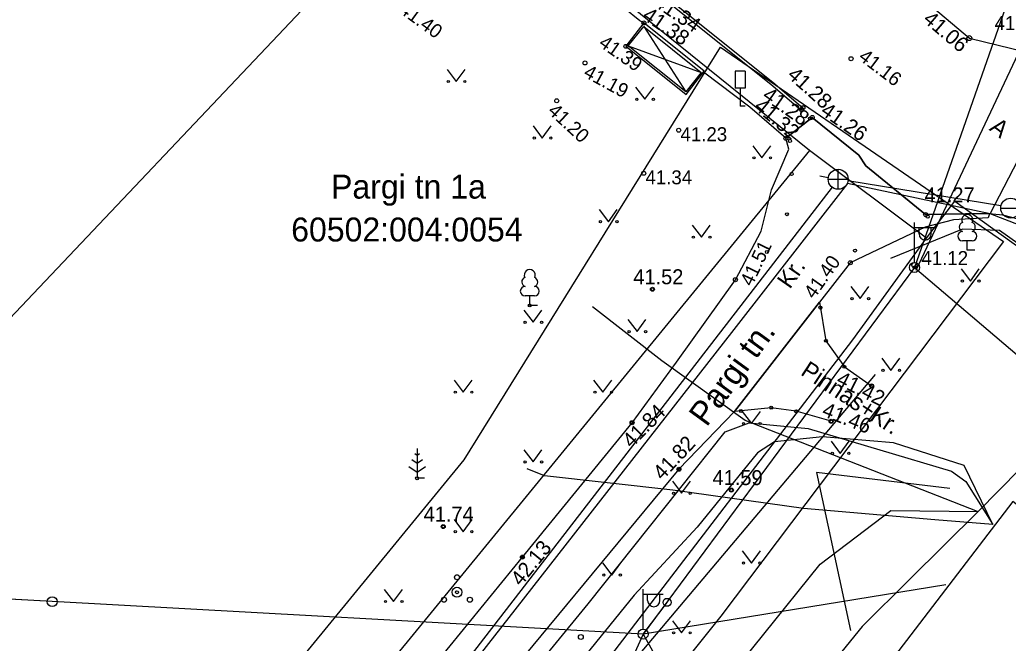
# Model space of a CAD drawing. Extents: x 641898 to 642452, y 6471715 to 6472255.
# Drawn here: x 642021.88 to 642071.44, y 6472004.79 to 6472036.05 of the extents above; entities that cross this region are included whole.
import ezdxf

# ---------------------------------------------------------------- set-up
doc = ezdxf.new("R2010")
doc.units = 0
for name, color, linetype in [('HALJASTUS', 7, 'Continuous'), ('HOONE', 7, 'Continuous'), ('KKAEV', 7, 'Continuous'), ('KORGUS-EH2000', 7, 'Continuous'), ('KTRASS', 7, 'Continuous'), ('LIIKLUS', 7, 'Continuous'), ('MOOTMPUNKT', 7, 'Continuous'), ('MOOTPIIR', 7, 'Continuous'), ('MPOHULIIN', 7, 'Continuous'), ('PIIR', 7, 'Continuous'), ('POST', 7, 'Continuous'), ('PUU', 7, 'Continuous'), ('RAJATIS', 7, 'Continuous'), ('SIOHULIIN', 7, 'Continuous'), ('SITRASS', 7, 'Continuous'), ('TEE', 7, 'Continuous'), ('VTRASS', 7, 'Continuous')]:
    doc.layers.add(name, color=color, linetype=linetype)

msp = doc.modelspace()

# ---------------------------------------------------------------- linework, layer by layer
at = {"layer": 'HALJASTUS'}
for p, q in [((642043.306, 6472033.563), (642043.77, 6472032.957)), ((642043.77, 6472032.957), (642044.215, 6472033.563)), ((642052.761, 6472032.671), (642053.224, 6472032.064)), ((642053.224, 6472032.064), (642053.67, 6472032.671)), ((642047.619, 6472030.728), (642048.083, 6472030.121)), ((642048.083, 6472030.121), (642048.528, 6472030.728)), ((642058.631, 6472029.735), (642059.095, 6472029.129)), ((642059.095, 6472029.129), (642059.54, 6472029.735)), ((642050.934, 6472026.534), (642051.398, 6472025.928)), ((642051.398, 6472025.928), (642051.843, 6472026.534)), ((642055.596, 6472025.762), (642056.06, 6472025.155)), ((642056.06, 6472025.155), (642056.505, 6472025.762)), ((642069.081, 6472023.561), (642069.545, 6472022.954)), ((642069.545, 6472022.954), (642069.99, 6472023.561)), ((642063.551, 6472022.676), (642064.015, 6472022.069)), ((642064.015, 6472022.069), (642064.46, 6472022.676)), ((642047.157, 6472021.488), (642047.621, 6472020.882)), ((642047.621, 6472020.882), (642048.066, 6472021.488)), ((642052.372, 6472021.023), (642052.835, 6472020.416)), ((642052.835, 6472020.416), (642053.281, 6472021.023)), ((642065.1, 6472019.079), (642065.563, 6472018.473)), ((642065.563, 6472018.473), (642066.009, 6472019.079)), ((642043.657, 6472017.988), (642044.121, 6472017.382)), ((642044.121, 6472017.382), (642044.566, 6472017.988)), ((642050.657, 6472017.988), (642051.121, 6472017.382)), ((642051.121, 6472017.382), (642051.566, 6472017.988)), ((642058.105, 6472016.418), (642058.569, 6472015.811)), ((642058.569, 6472015.811), (642059.014, 6472016.418)), ((642047.157, 6472014.488), (642047.621, 6472013.882)), ((642047.621, 6472013.882), (642048.066, 6472014.488)), ((642062.557, 6472014.92), (642063.02, 6472014.313)), ((642063.02, 6472014.313), (642063.466, 6472014.92)), ((642054.605, 6472012.918), (642055.069, 6472012.311)), ((642055.069, 6472012.311), (642055.514, 6472012.918)), ((642043.657, 6472010.988), (642044.121, 6472010.382)), ((642044.121, 6472010.382), (642044.566, 6472010.988)), ((642058.105, 6472009.418), (642058.569, 6472008.811)), ((642058.569, 6472008.811), (642059.014, 6472009.418)), ((642051.105, 6472008.819), (642051.569, 6472008.212)), ((642051.569, 6472008.212), (642052.014, 6472008.819)), ((642040.157, 6472007.488), (642040.621, 6472006.882)), ((642040.621, 6472006.882), (642041.066, 6472007.488)), ((642054.605, 6472005.918), (642055.069, 6472005.311)), ((642055.069, 6472005.311), (642055.514, 6472005.918))]:
    msp.add_line(p, q, dxfattribs=at)
for points in [[(642081.398, 6472012.884), (642083.689, 6472015.541), (642075.888, 6472022.02), (642071.009, 6472025.489), (642069.155, 6472025.558), (642065.54, 6472024.078)], [(642068.519, 6472012.551), (642061.836, 6472013.345), (642063.534, 6472005.431)]]:
    msp.add_lwpolyline(points, dxfattribs=at)
for centre in [(642043.369, 6472032.957), (642044.197, 6472032.957), (642052.823, 6472032.064), (642053.652, 6472032.064), (642047.682, 6472030.121), (642048.511, 6472030.121), (642058.694, 6472029.129), (642059.523, 6472029.129), (642050.997, 6472025.928), (642051.825, 6472025.928), (642055.658, 6472025.155), (642056.487, 6472025.155), (642069.144, 6472022.954), (642069.972, 6472022.954), (642063.614, 6472022.069), (642064.443, 6472022.069), (642047.22, 6472020.882), (642048.049, 6472020.882), (642052.434, 6472020.416), (642053.263, 6472020.416), (642065.162, 6472018.473), (642065.991, 6472018.473), (642043.72, 6472017.382), (642044.549, 6472017.382), (642050.72, 6472017.382), (642051.549, 6472017.382), (642058.168, 6472015.811), (642058.997, 6472015.811), (642062.619, 6472014.313), (642063.448, 6472014.313), (642047.22, 6472013.882), (642048.049, 6472013.882), (642054.668, 6472012.311), (642055.497, 6472012.311), (642043.72, 6472010.382), (642044.549, 6472010.382), (642058.168, 6472008.811), (642058.997, 6472008.811), (642051.168, 6472008.212), (642051.997, 6472008.212), (642040.22, 6472006.882), (642041.049, 6472006.882), (642054.668, 6472005.311), (642055.497, 6472005.311)]:
    msp.add_circle(centre, 0.055, dxfattribs=at)
at = {"layer": 'HOONE'}
msp.add_lwpolyline([(642065.09, 6472003.293), (642089.074, 6471984.663), (642095.654, 6471993.274), (642071.669, 6472011.904), (642065.09, 6472003.293)], dxfattribs=at)
at = {"layer": 'KKAEV'}
for p, q in [((642062.915, 6472027.554), (642062.915, 6472028.554)), ((642062.415, 6472028.054), (642063.415, 6472028.054)), ((642071.064, 6472026.609), (642072.064, 6472026.609))]:
    msp.add_line(p, q, dxfattribs=at)
for centre in [(642062.915, 6472028.054), (642071.564, 6472026.609)]:
    msp.add_circle(centre, 0.5, dxfattribs=at)
at = {"layer": 'KORGUS-EH2000'}
for centre, radius in [((642053.173, 6472035.891), 0.1), ((642052.271, 6472034.721), 0.1), ((642069.493, 6472035.132), 0.125), ((642050.223, 6472033.886), 0.1), ((642063.56, 6472034.099), 0.1), ((642048.805, 6472031.99), 0.1), ((642061.084, 6472031.548), 0.1), ((642061.148, 6472031.643), 0.1), ((642061.62, 6472031.153), 0.1), ((642054.921, 6472030.516), 0.1), ((642060.293, 6472030.111), 0.1), ((642053.165, 6472028.353), 0.1), ((642067.3, 6472026.288), 0.1), ((642063.525, 6472023.868), 0.1), ((642066.738, 6472023.755), 0.125), ((642057.761, 6472023.02), 0.1), ((642053.605, 6472022.541), 0.1), ((642064.594, 6472017.696), 0.1), ((642052.582, 6472015.849), 0.1), ((642062.564, 6472015.919), 0.1), ((642054.934, 6472013.517), 0.1), ((642057.56, 6472012.47), 0.1), ((642043.116, 6472010.641), 0.1), ((642047.085, 6472009.109), 0.1)]:
    msp.add_circle(centre, radius, dxfattribs=at)
at = {"layer": 'KTRASS'}
for points in [[(642062.421, 6472028.134), (642061.996, 6472028.203)], [(642071.076, 6472026.716), (642063.408, 6472027.973)], [(642062.609, 6472027.658), (642036.877, 6471994.318)], [(642033.098, 6471980.696), (642064.794, 6472018.263)]]:
    msp.add_lwpolyline(points, dxfattribs=at)
at = {"layer": 'LIIKLUS'}
for p, q in [((642057.749, 6472033.468), (642057.749, 6472032.618)), ((642058.249, 6472033.468), (642057.749, 6472033.468)), ((642058.249, 6472033.468), (642058.249, 6472032.618)), ((642058.249, 6472032.618), (642057.749, 6472032.618)), ((642057.999, 6472032.618), (642057.999, 6472031.718)), ((642058.249, 6472031.718), (642057.999, 6472031.718))]:
    msp.add_line(p, q, dxfattribs=at)
at = {"layer": 'MOOTMPUNKT'}
for centre in [(642061.504, 6472031.105), (642060.499, 6472029.974), (642060.583, 6472028.318), (642060.347, 6472026.3), (642067.404, 6472026.178), (642059.341, 6472024.41), (642063.761, 6472024.481), (642066.743, 6472023.634), (642053.605, 6472022.541), (642047.455, 6472021.731), (642062.025, 6472021.618), (642062.299, 6472019.958), (642063.23, 6472018.655), (642064.594, 6472017.696), (642058.036, 6472016.434), (642059.56, 6472016.601), (642060.803, 6472016.425), (642062.564, 6472015.919), (642052.582, 6472015.849), (642054.934, 6472013.517), (642041.808, 6472013.061), (642057.56, 6472012.47), (642043.116, 6472010.641), (642047.085, 6472009.109), (642043.805, 6472007.348)]:
    msp.add_circle(centre, 0.075, dxfattribs=at)
at = {"layer": 'MOOTPIIR'}
msp.add_lwpolyline([(642057.038, 6472006.154), (641981.622, 6471911.832), (641974.173, 6471900.785), (641991.385, 6471889.279), (641976.334, 6471874.678), (641962.442, 6471882.56), (641955.727, 6471896.847), (641967.922, 6471920.935), (642044.157, 6472013.993), (642057.02, 6472034.672), (642071.202, 6472024.941)], close=True, dxfattribs=at)
at = {"layer": 'MPOHULIIN'}
for p, q in [((642023.51, 6472006.876), (642005.441, 6472007.868)), ((642053.137, 6472005.249), (642023.51, 6472006.876))]:
    msp.add_line(p, q, dxfattribs=at)
for points in [[(642026.721, 6472180.493), (642057.005, 6472135.15), (642092.759, 6472082.232), (642082.032, 6472055.789), (642066.817, 6472023.473)], [(642074.552, 6472045.947), (642066.743, 6472023.634), (642053.137, 6472005.249)], [(642066.743, 6472023.634), (642090.685, 6472003.265), (642087.608, 6471999.648)], [(642053.137, 6472005.249), (642037.493, 6471970.833), (642031.254, 6471937.857), (642022.97, 6471901.239), (642022.97, 6471901.239)], [(642053.137, 6472005.249), (642065.494, 6471983.242), (642060.226, 6471969.422)]]:
    msp.add_lwpolyline(points, dxfattribs=at)
at = {"layer": 'PIIR'}
for p, q in [((642043.28, 6472044.21), (642015.37, 6472014.73)), ((642061.48, 6472029.49), (642043.28, 6472044.21)), ((642061.48, 6472029.49), (642027.1, 6471987.54)), ((642067.35, 6472025.11), (642061.48, 6472029.49)), ((642067.35, 6472025.11), (642068.76, 6472026.95)), ((642068.76, 6472026.95), (642119.65, 6471990.44)), ((642063.65, 6472020.01), (642067.35, 6472025.11)), ((642045.38, 6471996.16), (642063.65, 6472020.01))]:
    msp.add_line(p, q, dxfattribs=at)
at = {"layer": 'POST'}
for p, q in [((642066.743, 6472023.884), (642066.743, 6472025.884)), ((642066.743, 6472025.634), (642067.743, 6472025.634)), ((642066.97, 6472025.313), (642066.97, 6472025.634)), ((642067.582, 6472025.313), (642067.582, 6472025.634)), ((642066.743, 6472023.634), (642066.743, 6472023.634)), ((642053.137, 6472005.499), (642053.137, 6472007.499)), ((642053.137, 6472007.249), (642054.137, 6472007.249)), ((642053.364, 6472006.928), (642053.364, 6472007.249)), ((642053.976, 6472006.928), (642053.976, 6472007.249)), ((642053.137, 6472005.249), (642053.137, 6472005.249))]:
    msp.add_line(p, q, dxfattribs=at)
msp.add_lwpolyline([(642053.137, 6472005.249), (642054.337, 6472006.842)], dxfattribs=at)
for centre, radius in [((642066.743, 6472023.634), 0.25), ((642023.51, 6472006.876), 0.25), ((642054.337, 6472006.842), 0.2), ((642053.137, 6472005.249), 0.25)]:
    msp.add_circle(centre, radius, dxfattribs=at)
for centre in [(642067.276, 6472025.313), (642053.67, 6472006.928)]:
    msp.add_arc(centre, 0.306, 180, 0, dxfattribs=at)
at = {"layer": 'PUU'}
for p, q in [((642069.629, 6472024.967), (642069.149, 6472024.967)), ((642069.389, 6472024.492), (642069.389, 6472024.967)), ((642069.769, 6472024.492), (642069.389, 6472024.492)), ((642047.695, 6472022.206), (642047.215, 6472022.206)), ((642047.455, 6472021.731), (642047.455, 6472022.206)), ((642047.835, 6472021.731), (642047.455, 6472021.731)), ((642041.808, 6472014.561), (642041.808, 6472013.061)), ((642041.808, 6472013.811), (642041.541, 6472013.989)), ((642041.808, 6472014.211), (642041.684, 6472014.294)), ((642041.932, 6472014.294), (642041.808, 6472014.211)), ((642042.075, 6472013.989), (642041.808, 6472013.811)), ((642041.384, 6472013.65), (642041.808, 6472013.368)), ((642041.808, 6472013.368), (642042.232, 6472013.65)), ((642042.168, 6472013.061), (642041.808, 6472013.061))]:
    msp.add_line(p, q, dxfattribs=at)
for centre, radius in [((642043.805, 6472008.098), 0.125), ((642043.805, 6472007.348), 0.25), ((642043.155, 6472006.973), 0.125), ((642044.455, 6472006.973), 0.125), ((642050.014, 6472005.104), 0.125)]:
    msp.add_circle(centre, radius, dxfattribs=at)
for centre, radius, start, end in [((642069.219, 6472025.665), 0.233, 109.0217, 253.1415), ((642069.389, 6472026.012), 0.277, 332.5799, 207.4201), ((642069.559, 6472025.665), 0.233, 286.8508, 70.9859), ((642069.152, 6472025.204), 0.238, 90.0016, 269.3953), ((642069.626, 6472025.204), 0.238, 270.6047, 89.9984), ((642047.455, 6472023.251), 0.277, 332.5799, 207.4201), ((642047.285, 6472022.904), 0.233, 109.0217, 253.1415), ((642047.625, 6472022.904), 0.233, 286.8508, 70.9859), ((642047.218, 6472022.443), 0.238, 90.0016, 269.3953), ((642047.692, 6472022.443), 0.238, 270.6047, 89.9984)]:
    msp.add_arc(centre, radius, start, end, dxfattribs=at)
at = {"layer": 'RAJATIS'}
for points in [[(642053.173, 6472035.891), (642052.271, 6472034.721), (642055.296, 6472032.298), (642056.198, 6472033.468), (642053.173, 6472035.891)], [(642053.173, 6472035.711), (642056.05, 6472033.405), (642055.272, 6472032.434), (642052.394, 6472034.74), (642053.173, 6472035.711)], [(642053.173, 6472035.711), (642055.272, 6472032.434)], [(642052.394, 6472034.74), (642056.05, 6472033.405)]]:
    msp.add_lwpolyline(points, dxfattribs=at)
at = {"layer": 'SIOHULIIN'}
for points in [[(642066.743, 6472023.634), (642053.137, 6472005.249), (642023.51, 6472006.876)], [(642023.51, 6472006.876), (642005.441, 6472007.868)], [(642068.317, 6472007.721), (642053.137, 6472005.249)]]:
    msp.add_lwpolyline(points, dxfattribs=at)
at = {"layer": 'SITRASS'}
for points in [[(642069.897, 6472011.402), (642058.247, 6472015.961), (642054.069, 6472018.954), (642050.596, 6472021.656)], [(641950.498, 6471878.962), (641953.395, 6471882.884), (641960.326, 6471892.01), (641966.709, 6471900.548), (641975.149, 6471912.047), (641977.497, 6471915.401), (641982.148, 6471922.194), (641989.859, 6471932.438), (641996.556, 6471940.729), (642003.855, 6471950.395), (642007.644, 6471955.7), (642012.462, 6471961.683), (642019.884, 6471970.473), (642026.992, 6471979.225), (642031.388, 6471984.26), (642035.513, 6471988.868), (642043.437, 6471998.27), (642050.38, 6472006.769), (642057.251, 6472015.394), (642058.446, 6472015.84), (642061.412, 6472015.551), (642068.597, 6472013.427), (642069.315, 6472012.909), (642070.672, 6472010.753)], [(642070.672, 6472010.753), (642069.227, 6472013.708), (642065.692, 6472014.833), (642062.135, 6472015.136), (642059.724, 6472014.885), (642058.87, 6472014.337), (642055.853, 6472010.608), (642052.687, 6472007.205), (642042.715, 6471994.906), (642034.723, 6471986.377), (642026.899, 6471976.868), (642018.808, 6471967.026), (642008.192, 6471953.937), (641999.439, 6471942.057), (641991.934, 6471931.576), (641983.118, 6471919.561), (641974.037, 6471907.19), (641967.163, 6471898.052), (641963.02, 6471893.54), (641954.445, 6471881.908), (641951.759, 6471878.129)], [(642070.672, 6472010.753), (642067.762, 6472010.981), (642061.185, 6472011.544), (642054.628, 6472012.47), (642048.194, 6472013.187), (642047.317, 6472013.539)], [(642077.195, 6472010.417), (642072.032, 6472013.527), (642069.942, 6472011.402)], [(641949.242, 6471879.792), (641954.7, 6471888.984), (641972.051, 6471914.076), (641975.437, 6471918.798), (641975.45, 6471918.82), (641981.83, 6471927.71), (641981.832, 6471927.717), (641995.496, 6471946.773), (642011.112, 6471968.077), (642016.054, 6471972.628), (642019.836, 6471976.17), (642023.739, 6471980.511), (642028.082, 6471985.962), (642033.438, 6471992.196), (642037.782, 6471997.193), (642043.02, 6471996.48), (642050.924, 6471995.376), (642056.37, 6472001.743), (642062.014, 6472008.762), (642063.81, 6472010.12), (642065.56, 6472011.44), (642069.94, 6472011.4)], [(642069.94, 6472011.4), (642066.51, 6472008), (642064.116, 6472005.626), (642058.601, 6471998.849), (642055.997, 6471995.566)]]:
    msp.add_lwpolyline(points, dxfattribs=at)
at = {"layer": 'TEE'}
for points in [[(642047.12, 6472042.756), (642047.212, 6472042.874), (642048.774, 6472041.661), (642054.223, 6472037.267), (642059.637, 6472032.921), (642061.148, 6472031.643), (642061.051, 6472031.528), (642059.542, 6472032.805), (642054.129, 6472037.15), (642048.681, 6472041.543), (642047.12, 6472042.756)], [(642061.334, 6472042.026), (642069.493, 6472035.132), (642072.316, 6472034.445), (642073.376, 6472033.836), (642074.504, 6472035.529), (642073.973, 6472036.136)], [(642127.755, 6471983.25), (642118.56, 6471990.787), (642112.034, 6471995.922), (642104.507, 6472001.966), (642102.538, 6472003.592), (642099.411, 6472006.017), (642092.935, 6472011.037), (642082.111, 6472019.423), (642074.673, 6472025.315), (642072.485, 6472026.831), (642072.011, 6472026.035), (642071.166, 6472026.263), (642070.297, 6472026.346), (642067.3, 6472026.288), (642064.299, 6472028.73), (642063.954, 6472029.272), (642061.62, 6472031.153), (642060.293, 6472030.111), (642058.489, 6472031.665), (642056.171, 6472033.433), (642056.198, 6472033.468), (642053.173, 6472035.891), (642052.964, 6472035.998), (642047.466, 6472040.459)], [(642038.794, 6471998.949), (642047.085, 6472009.109), (642052.582, 6472015.849), (642054.803, 6472018.878), (642057.761, 6472023.02), (642059.055, 6472025.446), (642059.567, 6472027.518), (642060.438, 6472029.558), (642060.293, 6472030.111), (642061.62, 6472031.153), (642063.954, 6472029.272), (642064.299, 6472028.73), (642067.3, 6472026.288), (642070.297, 6472026.346), (642070.509, 6472026.326), (642070.439, 6472026.116), (642068.698, 6472026.028), (642067.271, 6472025.656), (642063.525, 6472023.868), (642061.981, 6472021.886), (642057.71, 6472016.404), (642054.934, 6472013.517), (642041.088, 6471996.808)], [(642062.564, 6472015.919), (642060.803, 6472016.425), (642059.56, 6472016.601), (642057.71, 6472016.404), (642061.981, 6472021.886), (642062.299, 6472019.958), (642063.23, 6472018.655), (642064.594, 6472017.696)]]:
    msp.add_lwpolyline(points, dxfattribs=at)
at = {"layer": 'VTRASS'}
for points in [[(642070.54, 6472026.319), (642075.225, 6472035.385), (642076.78, 6472036.904), (642080.024, 6472041.161)], [(642131.146, 6471978.791), (642122.669, 6471985.738), (642108.487, 6471997.357), (642100.73, 6472003.718), (642086.367, 6472014.732), (642072.004, 6472025.747), (642070.54, 6472026.319), (642063.386, 6472027.837), (642057.563, 6472020.38), (642046.398, 6472006.083), (642029.41, 6471984.33), (642022.753, 6471976.477), (642013.331, 6471964.779), (642003.99, 6471953.421), (641999.884, 6471948.226), (641984.12, 6471925.503), (641973.431, 6471931.653), (641967.433, 6471935.11)]]:
    msp.add_lwpolyline(points, dxfattribs=at)

# ---------------------------------------------------------------- texts
at = {"layer": 'KORGUS-EH2000'}
for s, height, rotation, p in [('41.40', 0.7, 323.8646, (642040.852, 6472036.453)), ('41.34', 0.75, 325.7843, (642053.616, 6472036.788)), ('41.38', 0.75, 325.8929, (642053.05, 6472036.128)), ('41.06', 0.75, 319.6096, (642067.129, 6472035.995)), ('41.39', 0.7, 324.8364, (642050.862, 6472034.766)), ('41.16', 0.7, 322.8034, (642063.89, 6472034.091)), ('41.19', 0.7, 331.3017, (642050.097, 6472033.232)), ('41.28', 0.75, 318.0848, (642060.316, 6472033.21)), ('41.28', 0.75, 325.2441, (642059.06, 6472032.125)), ('41.32', 0.75, 320.0921, (642058.654, 6472031.616)), ('41.20', 0.7, 317.1906, (642048.314, 6472031.418)), ('41.26', 0.75, 325.0393, (642061.983, 6472031.354)), ('41.51', 0.7, 64.3424, (642058.595, 6472022.642)), ('41.40', 0.7, 54.5829, (642061.708, 6472022.01)), ('41.42', 0.75, 333.0297, (642062.772, 6472017.809)), ('41.84', 0.75, 45.2622, (642052.553, 6472014.535)), ('41.46', 0.75, 338.2864, (642062.055, 6472016.21)), ('41.82', 0.75, 46.8881, (642054.103, 6472012.924)), ('42.13', 0.75, 50.9595, (642047.012, 6472007.612))]:
    msp.add_text(s, height=height, rotation=rotation, dxfattribs=at).set_placement(p)
for s, height, p in [('41.18', 0.7, (642070.759, 6472035.538)), ('41.23', 0.7, (642055.008, 6472029.965)), ('41.34', 0.7, (642053.252, 6472027.802)), ('41.27', 0.75, (642067.247, 6472026.896)), ('41.12', 0.7, (642067.088, 6472023.755)), ('41.52', 0.75, (642052.645, 6472022.791)), ('41.59', 0.75, (642056.617, 6472012.72)), ('41.74', 0.75, (642042.133, 6472010.891))]:
    msp.add_text(s, height=height, dxfattribs=at).set_placement(p)
at = {"layer": 'PIIR'}
for s, p in [('Pargi tn 1a', (642037.492, 6472027.086)), ('60502:004:0054', (642035.492, 6472024.935))]:
    msp.add_text(s, height=1.2, dxfattribs=at).set_placement(p)
at = {"layer": 'TEE'}
for s, height, rotation, p in [('A', 0.85, 322.4446, (642070.45, 6472030.542)), ('Kr.', 0.85, 55.2667, (642060.495, 6472022.513)), ('Pargi tn.', 1.2, 53.9397, (642056.32, 6472015.597)), ('Pinnas+Kr.', 0.85, 326.7745, (642060.985, 6472018.278))]:
    msp.add_text(s, height=height, rotation=rotation, dxfattribs=at).set_placement(p)

doc.saveas('drawing.dxf')
